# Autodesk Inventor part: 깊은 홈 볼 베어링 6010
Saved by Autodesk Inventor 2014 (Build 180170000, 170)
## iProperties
Created: 2026-05
Part Number: 깊은 홈 볼 베어링 6010
Material: 일반
Document SubType Name: Modeling
Designer: dg
Density: 1 g/cm^3
Appearance: 기본값
Author: dg
Author: jhkim
Description: 깊은 그루브 볼 베어링
Creation Date: 2026-04-27
Sending System: Autodesk Inventor 2027
Preprocessor: ST-DEVELOPER v20.1
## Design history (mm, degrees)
node "깊은 홈 볼 베어링 60101"
body "Solid1"
node "Solid1_1"
node "Solid1_2"
node "Solid1_3"
node "Solid1_4"
node "Solid1_5"
node "Solid1_6"
node "Solid1_7"
node "Solid1_8"
node "Solid1_9"
node "Solid1_10"
node "Solid1_11"
node "Solid1_12"
node "Solid1_13"
node "Solid1_14"
node "기준1"
node "기준2"
node "기준3"
node "기준4"
node "기준5"
node "기준6"
node "기준7"
node "기준8"
node "기준9"
node "기준10"
node "기준11"
node "기준12"
node "기준13"
node "기준14"
node "기준15"
